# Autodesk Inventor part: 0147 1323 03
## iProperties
Shininess: 70.0
Length Units: 11269
Angle Units: 11279
Time Units: 11290
Mass Units: 11283
Length Display Precision: 3
Angle Display Precision: 2
Created: 2000-12
Part Number: 0147 1323 03
Material: Steel, Mild
Description: Screw
Document SubType Name: Modeling
Designer: Joe M
Engineer: Joe M
Density: 0.0
Volumn: 0.0
Area: 0.0
PropertySet Name: Model Information
Control State: 0
Master: False
Checked Out: False
Title: Skruv
Author: Joe M
